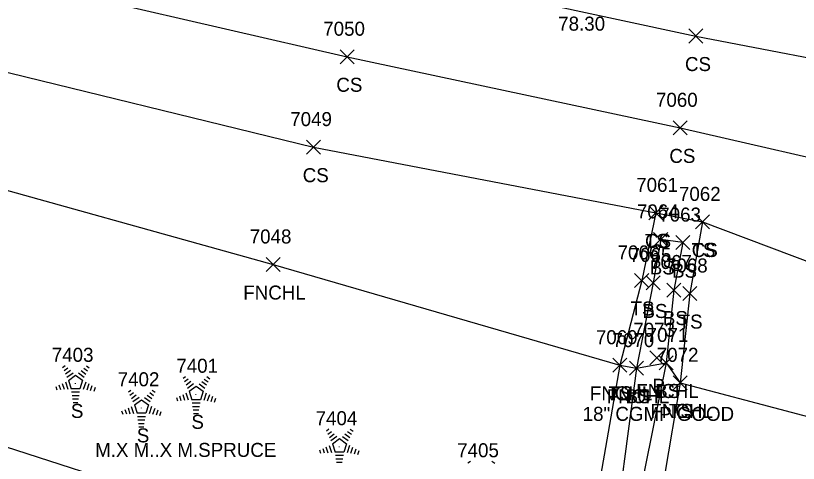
# Model space of a CAD drawing. Extents: x 1505656 to 1508446, y 700805 to 703031.
# Drawn here: x 1507608.7 to 1507720.3, y 701532.1 to 701595.9 of the extents above; entities that cross this region are included whole.
import ezdxf

# ---------------------------------------------------------------- set-up
doc = ezdxf.new("R2010")
doc.units = 0
for name, color, linetype in [('D_A', 7, 'Continuous'), ('D_C', 7, 'Continuous'), ('D_I', 7, 'Continuous'), ('D_TIC', 7, 'Continuous'), ('L_A', 7, 'Continuous'), ('L_C', 7, 'Continuous'), ('L_I', 7, 'Continuous'), ('L_TIC', 7, 'Continuous'), ('LELB', 7, 'Continuous'), ('LFNC', 7, 'Continuous'), ('LTC', 7, 'Continuous'), ('S_C', 7, 'Continuous')]:
    doc.layers.add(name, color=color, linetype=linetype)

msp = doc.modelspace()

# ---------------------------------------------------------------- linework, layer by layer
at = {"layer": 'D_TIC'}
for points in [[(1507699.12, 701546.11), (1507701.12, 701548.11)], [(1507701.12, 701546.11), (1507699.12, 701548.11)]]:
    msp.add_lwpolyline(points, dxfattribs=at)
at = {"layer": 'L_TIC'}
for points in [[(1507704.7, 701592), (1507706.7, 701594)], [(1507706.7, 701592), (1507704.7, 701594)], [(1507654.97, 701589.04), (1507656.97, 701591.04)], [(1507656.97, 701589.04), (1507654.97, 701591.04)], [(1507702.48, 701578.9), (1507704.48, 701580.9)], [(1507704.48, 701578.9), (1507702.48, 701580.9)], [(1507650.17, 701576.15), (1507652.17, 701578.15)], [(1507652.17, 701576.15), (1507650.17, 701578.15)], [(1507699.01, 701566.77), (1507701.01, 701568.77)], [(1507701.01, 701566.77), (1507699.01, 701568.77)], [(1507699.01, 701566.77), (1507701.01, 701568.77)], [(1507701.01, 701566.77), (1507699.01, 701568.77)], [(1507705.67, 701565.48), (1507707.67, 701567.48)], [(1507707.67, 701565.48), (1507705.67, 701567.48)], [(1507705.67, 701565.48), (1507707.67, 701567.48)], [(1507707.67, 701565.48), (1507705.67, 701567.48)], [(1507699.68, 701562.99), (1507701.68, 701564.99)], [(1507701.68, 701562.99), (1507699.68, 701564.99)], [(1507702.86, 701562.53), (1507704.86, 701564.53)], [(1507704.86, 701562.53), (1507702.86, 701564.53)], [(1507702.86, 701562.53), (1507704.86, 701564.53)], [(1507704.86, 701562.53), (1507702.86, 701564.53)], [(1507644.38, 701559.41), (1507646.38, 701561.41)], [(1507646.38, 701559.41), (1507644.38, 701561.41)], [(1507696.97, 701557.14), (1507698.97, 701559.14)], [(1507698.97, 701557.14), (1507696.97, 701559.14)], [(1507698.63, 701556.78), (1507700.63, 701558.78)], [(1507700.63, 701556.78), (1507698.63, 701558.78)], [(1507701.55, 701555.77), (1507703.55, 701557.77)], [(1507703.55, 701555.77), (1507701.55, 701557.77)], [(1507703.83, 701555.27), (1507705.83, 701557.27)], [(1507705.83, 701555.27), (1507703.83, 701557.27)], [(1507700.45, 701545.37), (1507702.45, 701547.37)], [(1507702.45, 701545.37), (1507700.45, 701547.37)], [(1507700.45, 701545.37), (1507702.45, 701547.37)], [(1507702.45, 701545.37), (1507700.45, 701547.37)], [(1507693.84, 701545.04), (1507695.84, 701547.04)], [(1507695.84, 701545.04), (1507693.84, 701547.04)], [(1507693.84, 701545.04), (1507695.84, 701547.04)], [(1507695.84, 701545.04), (1507693.84, 701547.04)], [(1507696.23, 701544.63), (1507698.23, 701546.63)], [(1507698.23, 701544.63), (1507696.23, 701546.63)], [(1507696.23, 701544.63), (1507698.23, 701546.63)], [(1507698.23, 701544.63), (1507696.23, 701546.63)], [(1507702.46, 701542.53), (1507704.46, 701544.53)], [(1507704.46, 701542.53), (1507702.46, 701544.53)], [(1507702.46, 701542.53), (1507704.46, 701544.53)], [(1507704.46, 701542.53), (1507702.46, 701544.53)]]:
    msp.add_lwpolyline(points, dxfattribs=at)
at = {"layer": 'LELB'}
for points in [[(1507371.82, 701631.2), (1507419.37, 701631.63), (1507454.54, 701624.79), (1507505.05, 701622.5), (1507556.06, 701615.76), (1507605.29, 701610.61), (1507659.37, 701602.95), (1507705.7, 701593), (1507760.19, 701582.5), (1507867, 701555.37), (1507918.17, 701539.42), (1507965.63, 701522.2), (1508016.59, 701504.14), (1508070.8, 701481.77), (1508118.11, 701461.28), (1508164.85, 701439.21), (1508217.28, 701414)], [(1507454.54, 701624.79), (1507504.74, 701612.91), (1507553.31, 701603.43), (1507603.85, 701602.08), (1507655.97, 701590.04), (1507703.48, 701579.9), (1507760.64, 701566.79), (1507809, 701557.31), (1507862.6, 701540.85), (1507913.87, 701525.11), (1507961.41, 701507.74), (1508011.25, 701488.42), (1508064.95, 701467.68), (1508110.8, 701446.82), (1508159.76, 701433), (1508184.08, 701421.84)], [(1507553.31, 701603.43), (1507601.29, 701589.31), (1507651.17, 701577.15), (1507700.01, 701567.77), (1507706.67, 701566.48), (1507755.13, 701548.25), (1507804.73, 701537.71), (1507857.08, 701521.39), (1507908.09, 701506.28), (1507956.13, 701490.86), (1508006.59, 701471.95), (1508058.56, 701454.54), (1508106.68, 701438.49), (1508127.36, 701424.8)], [(1507700.01, 701567.77), (1507697.97, 701558.14), (1507694.84, 701546.04), (1507690.25, 701519.56)], [(1507706.67, 701566.48), (1507704.83, 701556.27), (1507703.46, 701543.53), (1507698.99, 701517.09), (1507701.55, 701503.96)], [(1507703.86, 701563.53), (1507700.68, 701563.99), (1507699.63, 701557.78), (1507697.23, 701545.63), (1507693.59, 701517.97), (1507687.4, 701507.46), (1507681.76, 701493.99)], [(1507703.86, 701563.53), (1507702.55, 701556.77), (1507701.45, 701546.37), (1507695.59, 701517.19), (1507692.53, 701505.99), (1507690.02, 701491.91)], [(1507690.25, 701519.56), (1507678.23, 701514.35), (1507640.03, 701523.8), (1507594.65, 701538.46), (1507552.15, 701546.6), (1507515.48, 701560.34)]]:
    msp.add_lwpolyline(points, dxfattribs=at)
at = {"layer": 'LFNC'}
msp.add_lwpolyline([(1507316.28, 701641.94), (1507325.71, 701640.14), (1507335.33, 701637.87), (1507371.82, 701631.2), (1507412.81, 701624.01), (1507430.26, 701620.91), (1507449.32, 701615.51), (1507500.36, 701609.38), (1507547.47, 701587.34), (1507597.95, 701573.61), (1507645.38, 701560.41), (1507694.84, 701546.04), (1507697.23, 701545.63), (1507701.45, 701546.37), (1507703.46, 701543.53), (1507750.96, 701530.99)], dxfattribs=at)
at = {"layer": 'LTC'}
for p, q in [((1507615.35, 701545.74), (1507615.7, 701546)), ((1507615.56, 701545.27), (1507616.09, 701545.66)), ((1507615.77, 701544.81), (1507616.47, 701545.32)), ((1507618, 701545.28), (1507618.68, 701544.79)), ((1507618.37, 701545.63), (1507618.92, 701545.23)), ((1507618.75, 701545.98), (1507619.16, 701545.68)), ((1507615.98, 701544.34), (1507616.85, 701544.98)), ((1507616.2, 701543.89), (1507617.21, 701544.62)), ((1507617.21, 701544.62), (1507618.21, 701543.9)), ((1507617.63, 701544.94), (1507618.44, 701544.35)), ((1507632.54, 701544.18), (1507632.9, 701544.44)), ((1507632.75, 701543.71), (1507633.28, 701544.1)), ((1507635.57, 701544.07), (1507636.12, 701543.67)), ((1507635.94, 701544.42), (1507636.36, 701544.12)), ((1507614.38, 701543.02), (1507614.53, 701542.55)), ((1507614.83, 701543.24), (1507615.05, 701542.58)), ((1507615.29, 701543.45), (1507615.56, 701542.62)), ((1507615.75, 701543.67), (1507616.08, 701542.65)), ((1507616.2, 701543.89), (1507616.59, 701542.69)), ((1507618.21, 701543.9), (1507617.82, 701542.69)), ((1507618.65, 701543.63), (1507618.31, 701542.59)), ((1507619.09, 701543.38), (1507618.8, 701542.49)), ((1507619.54, 701543.13), (1507619.3, 701542.4)), ((1507619.98, 701542.88), (1507619.79, 701542.3)), ((1507632.96, 701543.25), (1507633.67, 701543.76)), ((1507633.17, 701542.78), (1507634.05, 701543.42)), ((1507633.4, 701542.33), (1507634.41, 701543.06)), ((1507634.41, 701543.06), (1507635.41, 701542.34)), ((1507634.83, 701543.38), (1507635.64, 701542.79)), ((1507635.2, 701543.72), (1507635.88, 701543.23)), ((1507617.82, 701542.69), (1507616.59, 701542.69)), ((1507617.78, 701542.19), (1507616.63, 701542.19)), ((1507624.75, 701542.25), (1507625.1, 701542.51)), ((1507624.96, 701541.78), (1507625.49, 701542.17)), ((1507625.17, 701541.32), (1507625.87, 701541.83)), ((1507627.4, 701541.79), (1507628.08, 701541.3)), ((1507627.78, 701542.14), (1507628.32, 701541.74)), ((1507628.15, 701542.49), (1507628.57, 701542.18)), ((1507632.49, 701541.89), (1507632.76, 701541.06)), ((1507632.94, 701542.11), (1507633.27, 701541.09)), ((1507633.4, 701542.33), (1507633.78, 701541.13)), ((1507635.41, 701542.34), (1507635.01, 701541.13)), ((1507635.84, 701542.07), (1507635.5, 701541.03)), ((1507636.29, 701541.82), (1507636, 701540.93)), ((1507617.7, 701541.69), (1507616.71, 701541.69)), ((1507617.61, 701541.19), (1507616.78, 701541.19)), ((1507617.53, 701540.69), (1507616.85, 701540.69)), ((1507625.38, 701540.85), (1507626.26, 701541.49)), ((1507625.6, 701540.4), (1507626.61, 701541.13)), ((1507626.61, 701541.13), (1507627.61, 701540.41)), ((1507627.03, 701541.44), (1507627.84, 701540.86)), ((1507631.58, 701541.46), (1507631.73, 701540.99)), ((1507632.03, 701541.68), (1507632.24, 701541.02)), ((1507635.01, 701541.13), (1507633.78, 701541.13)), ((1507634.98, 701540.63), (1507633.83, 701540.63)), ((1507636.73, 701541.57), (1507636.49, 701540.84)), ((1507637.18, 701541.32), (1507636.99, 701540.74)), ((1507623.78, 701539.53), (1507623.93, 701539.06)), ((1507624.24, 701539.74), (1507624.45, 701539.09)), ((1507624.69, 701539.96), (1507624.96, 701539.13)), ((1507625.15, 701540.18), (1507625.48, 701539.16)), ((1507625.6, 701540.4), (1507625.99, 701539.2)), ((1507627.61, 701540.41), (1507627.22, 701539.2)), ((1507628.05, 701540.14), (1507627.71, 701539.1)), ((1507628.49, 701539.89), (1507628.2, 701539)), ((1507628.94, 701539.64), (1507628.7, 701538.91)), ((1507634.89, 701540.13), (1507633.9, 701540.13)), ((1507634.81, 701539.63), (1507633.98, 701539.63)), ((1507627.22, 701539.2), (1507625.99, 701539.2)), ((1507627.18, 701538.7), (1507626.04, 701538.7)), ((1507629.38, 701539.38), (1507629.19, 701538.81)), ((1507634.72, 701539.13), (1507634.05, 701539.13)), ((1507627.1, 701538.2), (1507626.11, 701538.2)), ((1507627.01, 701537.7), (1507626.18, 701537.7)), ((1507626.93, 701537.2), (1507626.25, 701537.2)), ((1507652.99, 701536.69), (1507653.34, 701536.95)), ((1507653.2, 701536.23), (1507653.72, 701536.61)), ((1507653.41, 701535.76), (1507654.11, 701536.27)), ((1507655.64, 701536.24), (1507656.32, 701535.74)), ((1507656.01, 701536.59), (1507656.56, 701536.19)), ((1507656.38, 701536.93), (1507656.8, 701536.63)), ((1507653.61, 701535.3), (1507654.49, 701535.93)), ((1507653.84, 701534.84), (1507654.85, 701535.58)), ((1507654.85, 701535.58), (1507655.85, 701534.85)), ((1507655.27, 701535.89), (1507656.08, 701535.3)), ((1507652.02, 701533.97), (1507652.17, 701533.51)), ((1507652.47, 701534.19), (1507652.69, 701533.54)), ((1507652.93, 701534.41), (1507653.2, 701533.57)), ((1507653.38, 701534.62), (1507653.72, 701533.6)), ((1507653.84, 701534.84), (1507654.23, 701533.65)), ((1507655.85, 701534.85), (1507655.46, 701533.65)), ((1507656.29, 701534.58), (1507655.95, 701533.54)), ((1507656.73, 701534.33), (1507656.44, 701533.45)), ((1507657.17, 701534.08), (1507656.94, 701533.35)), ((1507655.46, 701533.65), (1507654.23, 701533.65)), ((1507655.42, 701533.15), (1507654.27, 701533.15)), ((1507657.62, 701533.83), (1507657.43, 701533.26)), ((1507655.33, 701532.65), (1507654.35, 701532.65)), ((1507655.25, 701532.15), (1507654.42, 701532.15)), ((1507673.19, 701532.12), (1507673.54, 701532.38)), ((1507676.58, 701532.37), (1507677, 701532.06))]:
    msp.add_line(p, q, dxfattribs=at)

# ---------------------------------------------------------------- texts
at = {"layer": 'D_A'}
msp.add_text('P', height=2, dxfattribs=at).set_placement((1507699.5, 701542.11))
at = {"layer": 'D_C'}
msp.add_text('18" CGMP GOOD', height=2, dxfattribs=at).set_placement((1507689.55, 701538.11))
at = {"layer": 'D_I'}
msp.add_text('7073', height=2, dxfattribs=at).set_placement((1507696.78, 701550.11))
at = {"layer": 'L_A'}
for s, p in [('CS', (1507704.15, 701588)), ('CS', (1507654.41, 701585.04)), ('CS', (1507701.92, 701574.9)), ('CS', (1507649.61, 701572.15)), ('TS', (1507698.42, 701562.77)), ('CS', (1507698.45, 701562.77)), ('TS', (1507705.08, 701561.48)), ('CS', (1507705.11, 701561.48)), ('BS', (1507699.12, 701558.99)), ('BS', (1507702.3, 701558.53)), ('BS', (1507702.3, 701558.53)), ('FNCHL', (1507641.13, 701555.41)), ('TS', (1507696.38, 701553.14)), ('BS', (1507698.08, 701552.78)), ('BS', (1507700.99, 701551.77)), ('TS', (1507703.24, 701551.27)), ('FNCHL', (1507690.58, 701541.04)), ('TS', (1507693.24, 701541.04)), ('FNCHL', (1507697.2, 701541.37)), ('BS', (1507699.89, 701541.37)), ('FNCHL', (1507692.98, 701540.63)), ('BS', (1507695.67, 701540.63)), ('S', (1507616.54, 701538.53)), ('FNCHL', (1507699.21, 701538.53)), ('TS', (1507701.87, 701538.53)), ('S', (1507633.73, 701536.97)), ('S', (1507625.94, 701535.04))]:
    msp.add_text(s, height=2, dxfattribs=at).set_placement(p)
at = {"layer": 'L_C'}
msp.add_text('M.X M..X M.SPRUCE', height=2, dxfattribs=at).set_placement((1507619.99, 701532.97))
at = {"layer": 'L_I'}
for s, p in [('7050', (1507652.54, 701593.04)), ('7060', (1507700.01, 701582.9)), ('7049', (1507647.83, 701580.15)), ('7061', (1507697.19, 701570.77)), ('7061', (1507697.19, 701570.77)), ('7062', (1507703.29, 701569.48)), ('7062', (1507703.29, 701569.48)), ('7064', (1507697.29, 701566.99)), ('7063', (1507700.48, 701566.53)), ('7063', (1507700.48, 701566.53)), ('7048', (1507642.05, 701563.41)), ('7066', (1507694.53, 701561.14)), ('7065', (1507696.25, 701560.78)), ('7067', (1507699.17, 701559.77)), ('7068', (1507701.44, 701559.27)), ('7069', (1507691.44, 701549.04)), ('7069', (1507691.44, 701549.04)), ('7070', (1507693.81, 701548.63)), ('7070', (1507693.81, 701548.63)), ('7071', (1507698.68, 701549.37)), ('7071', (1507698.68, 701549.37)), ('7403', (1507613.81, 701546.53)), ('7072', (1507700.12, 701546.53)), ('7072', (1507700.12, 701546.53)), ('7401', (1507631.58, 701544.97)), ('7402', (1507623.21, 701543.04)), ('7404', (1507651.45, 701537.49)), ('7405', (1507671.65, 701532.92))]:
    msp.add_text(s, height=2, dxfattribs=at).set_placement(p)
at = {"layer": 'LTC'}
for p in [(1507617.09, 701543.64), (1507634.29, 701542.08), (1507626.5, 701540.14), (1507654.73, 701534.59)]:
    msp.add_text('.', height=1.04, rotation=270, dxfattribs=at).set_placement(p)
at = {"layer": 'S_C'}
msp.add_text('78.30', height=2, dxfattribs=at).set_placement((1507686.06, 701593.76))

doc.saveas('drawing.dxf')
